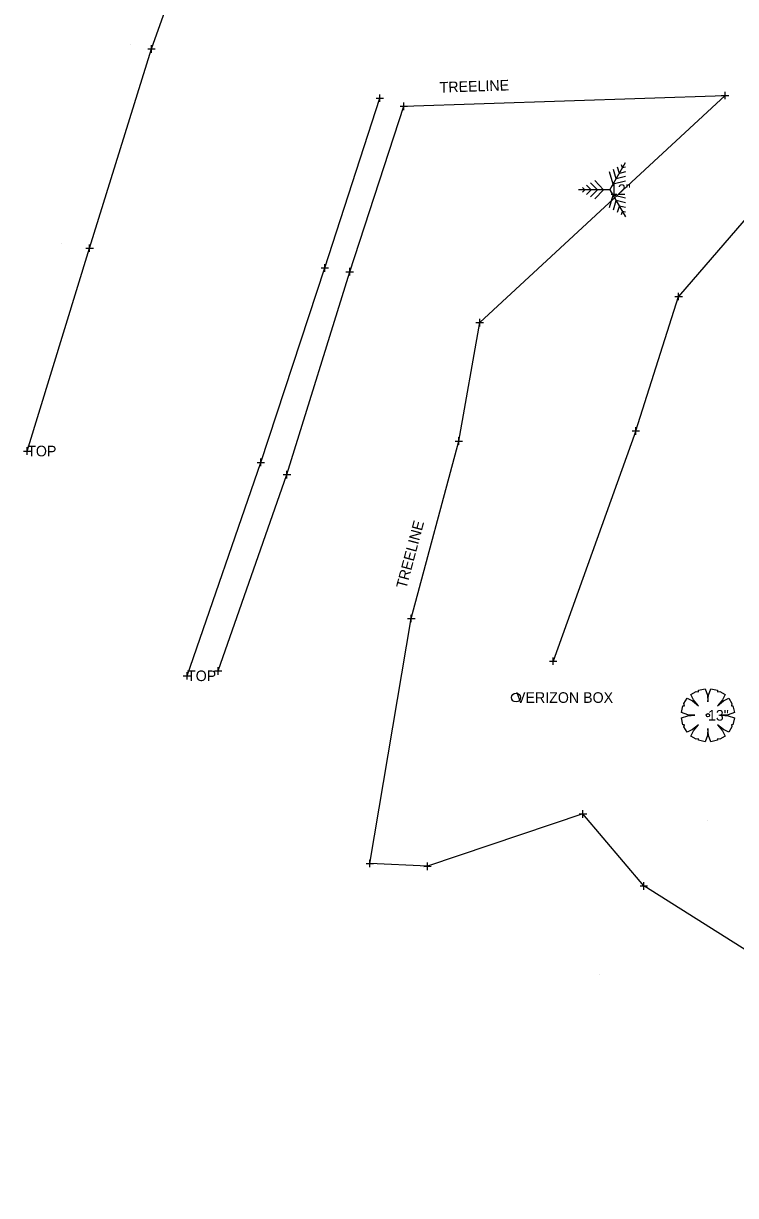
# Model space of a CAD drawing. Extents: x 1738496 to 1739092, y 463766 to 465141.
# Drawn here: x 1738868.7 to 1738989.4, y 464674 to 464872.7 of the extents above; entities that cross this region are included whole.
import ezdxf

# ---------------------------------------------------------------- set-up
doc = ezdxf.new("R2010")
doc.units = 0
for name, color, linetype in [('S_Survey_Shot', 7, 'Continuous'), ('S_Terrain_Breaklines', 7, 'Continuous'), ('S_Terrain_Flow_Arrows', 7, 'Continuous'), ('S_Terrain_Holes', 7, 'Continuous'), ('S_Terrain_Low_Points', 7, 'Continuous'), ('S_Terrain_Major_Contours_Label', 7, 'Continuous'), ('S_Terrain_Triangle_Vertices', 7, 'Continuous'), ('S_Terrain_Triangles', 7, 'Continuous'), ('S_Terrain_XSC', 7, 'Continuous')]:
    doc.layers.add(name, color=color, linetype=linetype)

msp = doc.modelspace()

# ---------------------------------------------------------------- linework, layer by layer
at = {"layer": 'S_Terrain_Breaklines'}
msp.add_lwpolyline([(1739055.7, 464674.03), (1739025.48, 464693.91), (1738973.83, 464726.51), (1738963.51, 464738.72), (1738937.19, 464729.84), (1738927.41, 464730.3)], dxfattribs=at)
at = {"layer": 'S_Terrain_Flow_Arrows'}
msp.add_circle((1738952.17, 464758.45), 0.749, dxfattribs=at)
at = {"layer": 'S_Terrain_Holes'}
for points in [[(1738901.72, 464762.97), (1738913.35, 464796.24), (1738923.99, 464830.65), (1738933.15, 464858.69), (1738987.58, 464860.51), (1738946.02, 464822.02)], [(1738927.41, 464730.3), (1738934.42, 464771.85), (1738942.48, 464801.94), (1738946.02, 464822.02)]]:
    msp.add_lwpolyline(points, dxfattribs=at)
at = {"layer": 'S_Terrain_Low_Points'}
for points in [[(1738869.35, 464800.24), (1738879.93, 464834.63), (1738890.41, 464868.41), (1738903.41, 464904.91), (1738913.32, 464936.3), (1738923.72, 464968.23), (1738928.3, 464983.93)], [(1738896.43, 464762.14), (1738908.93, 464798.32), (1738919.77, 464831.29), (1738929.1, 464860.07)], [(1739087.13, 464818.77), (1739078.77, 464823.89), (1739071.6, 464846.14), (1739036.85, 464844.29), (1738992.9, 464841.73), (1738979.72, 464826.45)], [(1738972.48, 464803.65), (1738979.72, 464826.45)], [(1738972.48, 464803.65), (1738958.46, 464764.61)]]:
    msp.add_lwpolyline(points, dxfattribs=at)
at = {"layer": 'S_Terrain_Major_Contours_Label'}
msp.add_lwpolyline([(1738982.44, 464755.44), (1738981.27, 464755.53), (1738980.18, 464755.89), (1738980.45, 464757.07), (1738980.72, 464757.07), (1738980.63, 464757.43), (1738981.18, 464758.33), (1738982.08, 464757.88), (1738983.07, 464757.07), (1738982.26, 464758.06), (1738981.81, 464758.96), (1738982.71, 464759.5), (1738983.07, 464759.41), (1738983.07, 464759.68), (1738984.24, 464759.95), (1738984.6, 464758.87), (1738984.69, 464757.7), (1738984.78, 464758.87), (1738985.15, 464759.95), (1738986.32, 464759.68), (1738986.32, 464759.41), (1738986.68, 464759.5), (1738987.58, 464758.96), (1738987.13, 464758.06), (1738986.32, 464757.07), (1738987.31, 464757.88), (1738988.21, 464758.33), (1738988.75, 464757.43), (1738988.66, 464757.07), (1738988.93, 464757.07), (1738989.21, 464755.89), (1738988.12, 464755.53), (1738986.95, 464755.44), (1738988.12, 464755.35), (1738989.21, 464754.99), (1738988.93, 464753.82), (1738988.66, 464753.82), (1738988.75, 464753.46), (1738988.21, 464752.56), (1738987.31, 464753.01), (1738986.32, 464753.82), (1738987.13, 464752.83), (1738987.58, 464751.92), (1738986.68, 464751.38), (1738986.32, 464751.47), (1738986.32, 464751.2), (1738985.15, 464750.93), (1738984.78, 464752.01), (1738984.69, 464753.19), (1738984.6, 464752.01), (1738984.24, 464750.93), (1738983.07, 464751.2), (1738983.07, 464751.47), (1738982.71, 464751.38), (1738981.81, 464751.92), (1738982.26, 464752.83), (1738983.07, 464753.82), (1738982.08, 464753.01), (1738981.18, 464752.56), (1738980.63, 464753.46), (1738980.72, 464753.82), (1738980.45, 464753.82), (1738980.18, 464754.99), (1738981.27, 464755.35), (1738982.44, 464755.44)], dxfattribs=at)
msp.add_circle((1738984.69, 464755.44), 0.283, dxfattribs=at)
at = {"layer": 'S_Terrain_Triangle_Vertices'}
for p, q in [((1738968.08, 464844.55), (1738970.74, 464849.16)), ((1738968.61, 464845.47), (1738968.01, 464847.58)), ((1738969.15, 464846.39), (1738968.69, 464847.97)), ((1738969.68, 464847.31), (1738969.37, 464848.37)), ((1738970.74, 464847.58), (1738969.68, 464847.31)), ((1738970.21, 464848.24), (1738970.06, 464848.77)), ((1738970.74, 464848.37), (1738970.21, 464848.24)), ((1738964.89, 464844.55), (1738964.13, 464845.34)), ((1738965.95, 464844.55), (1738964.81, 464845.73)), ((1738967.01, 464844.55), (1738965.5, 464846.13)), ((1738970.74, 464846), (1738968.61, 464845.47)), ((1738970.74, 464846.79), (1738969.15, 464846.39)), ((1738968.08, 464844.55), (1738962.76, 464844.55)), ((1738963.82, 464844.55), (1738963.44, 464844.94)), ((1738963.44, 464844.15), (1738963.82, 464844.55)), ((1738964.13, 464843.76), (1738964.89, 464844.55)), ((1738964.81, 464843.36), (1738965.95, 464844.55)), ((1738965.5, 464842.97), (1738967.01, 464844.55)), ((1738968.01, 464841.52), (1738968.61, 464843.63)), ((1738968.08, 464844.55), (1738970.74, 464839.94)), ((1738970.74, 464843.1), (1738968.61, 464843.63)), ((1738968.69, 464841.12), (1738969.15, 464842.7)), ((1738970.74, 464842.31), (1738969.15, 464842.7)), ((1738969.37, 464840.73), (1738969.68, 464841.78)), ((1738970.74, 464841.52), (1738969.68, 464841.78)), ((1738970.06, 464840.33), (1738970.21, 464840.86)), ((1738970.74, 464840.73), (1738970.21, 464840.86))]:
    msp.add_line(p, q, dxfattribs=at)
at = {"layer": 'S_Terrain_Triangles'}
for p, q in [((1738886.79, 464869.08), (1738886.79, 464869.08)), ((1738875.23, 464835.4), (1738875.23, 464835.4)), ((1738984.53, 464737.56), (1738984.53, 464737.56)), ((1738966.28, 464711.51), (1738966.28, 464711.51))]:
    msp.add_line(p, q, dxfattribs=at)
at = {"layer": 'S_Terrain_XSC'}
for p, q in [((1738890.41, 464867.77), (1738890.41, 464869.04)), ((1738889.78, 464868.4), (1738891.05, 464868.41)), ((1738890.41, 464868.41), (1738890.41, 464868.41)), ((1738987.59, 464859.87), (1738987.58, 464861.15)), ((1738928.47, 464860.07), (1738929.74, 464860.08)), ((1738929.11, 464859.44), (1738929.1, 464860.71)), ((1738929.1, 464860.07), (1738929.1, 464860.07)), ((1738933.16, 464858.05), (1738933.15, 464859.32)), ((1738986.95, 464860.51), (1738988.22, 464860.51)), ((1738987.58, 464860.51), (1738987.58, 464860.51)), ((1738932.52, 464858.69), (1738933.79, 464858.69)), ((1738933.15, 464858.69), (1738933.15, 464858.69)), ((1738879.93, 464834), (1738879.93, 464835.27)), ((1738879.29, 464834.63), (1738880.57, 464834.63)), ((1738879.93, 464834.63), (1738879.93, 464834.63)), ((1738919.13, 464831.29), (1738920.4, 464831.29)), ((1738919.77, 464830.65), (1738919.76, 464831.92)), ((1738919.77, 464831.29), (1738919.77, 464831.29)), ((1738923.99, 464830.01), (1738923.99, 464831.29)), ((1738923.35, 464830.65), (1738924.62, 464830.65)), ((1738923.99, 464830.65), (1738923.99, 464830.65)), ((1738979.09, 464826.45), (1738980.36, 464826.45)), ((1738979.72, 464825.81), (1738979.72, 464827.09)), ((1738979.72, 464826.45), (1738979.72, 464826.45)), ((1738945.38, 464822.02), (1738946.66, 464822.02)), ((1738945.38, 464822.02), (1738946.66, 464822.02)), ((1738946.02, 464821.38), (1738946.02, 464822.66)), ((1738946.02, 464821.38), (1738946.02, 464822.66)), ((1738946.02, 464822.02), (1738946.02, 464822.02)), ((1738946.02, 464822.02), (1738946.02, 464822.02)), ((1738971.84, 464803.65), (1738973.11, 464803.65)), ((1738972.48, 464803.01), (1738972.48, 464804.29)), ((1738972.48, 464803.65), (1738972.48, 464803.65)), ((1738941.85, 464801.94), (1738943.12, 464801.94)), ((1738942.49, 464801.31), (1738942.48, 464802.58)), ((1738942.48, 464801.94), (1738942.48, 464801.94)), ((1738868.72, 464800.24), (1738869.99, 464800.24)), ((1738869.35, 464799.6), (1738869.35, 464800.88)), ((1738869.35, 464800.24), (1738869.35, 464800.24)), ((1738908.3, 464798.32), (1738909.57, 464798.32)), ((1738908.93, 464797.68), (1738908.93, 464798.95)), ((1738908.93, 464798.32), (1738908.93, 464798.32)), ((1738912.71, 464796.24), (1738913.99, 464796.24)), ((1738913.35, 464795.6), (1738913.35, 464796.87)), ((1738913.35, 464796.24), (1738913.35, 464796.24)), ((1738933.79, 464771.85), (1738935.06, 464771.86)), ((1738934.42, 464771.22), (1738934.42, 464772.49)), ((1738934.42, 464771.85), (1738934.42, 464771.85)), ((1738957.82, 464764.61), (1738959.1, 464764.61)), ((1738958.46, 464763.97), (1738958.46, 464765.25)), ((1738958.46, 464764.61), (1738958.46, 464764.61)), ((1738895.79, 464762.14), (1738897.06, 464762.14)), ((1738896.43, 464761.5), (1738896.43, 464762.77)), ((1738896.43, 464762.14), (1738896.43, 464762.14)), ((1738901.08, 464762.96), (1738902.35, 464762.97)), ((1738901.72, 464762.33), (1738901.71, 464763.6)), ((1738901.72, 464762.97), (1738901.72, 464762.97)), ((1738962.87, 464738.71), (1738964.14, 464738.72)), ((1738963.51, 464738.08), (1738963.5, 464739.35)), ((1738963.51, 464738.72), (1738963.51, 464738.72)), ((1738926.78, 464730.3), (1738928.05, 464730.31)), ((1738926.78, 464730.3), (1738928.05, 464730.31)), ((1738927.42, 464729.67), (1738927.41, 464730.94)), ((1738927.42, 464729.67), (1738927.41, 464730.94)), ((1738927.41, 464730.3), (1738927.41, 464730.3)), ((1738927.41, 464730.3), (1738927.41, 464730.3)), ((1738937.19, 464729.2), (1738937.19, 464730.47)), ((1738936.55, 464729.83), (1738937.82, 464729.84)), ((1738937.19, 464729.84), (1738937.19, 464729.84)), ((1738973.19, 464726.51), (1738974.46, 464726.52)), ((1738973.83, 464725.88), (1738973.82, 464727.15)), ((1738973.83, 464726.51), (1738973.83, 464726.51))]:
    msp.add_line(p, q, dxfattribs=at)

# ---------------------------------------------------------------- texts
at = {"layer": 'S_Survey_Shot'}
for rotation, p in [(1.9172, (1738939.26, 464860.99)), (74.9988, (1738933.57, 464776.8))]:
    msp.add_text('TREELINE', height=1.8, rotation=rotation, dxfattribs=at).set_placement(p)
for s, p in [('12"', (1738968.08, 464843.65)), ('TOP', (1738869.35, 464799.34)), ('TOP', (1738896.43, 464761.24)), ('VERIZON BOX', (1738952.17, 464757.55)), ('13"', (1738984.69, 464754.54))]:
    msp.add_text(s, height=1.8, dxfattribs=at).set_placement(p)

doc.saveas('drawing.dxf')
